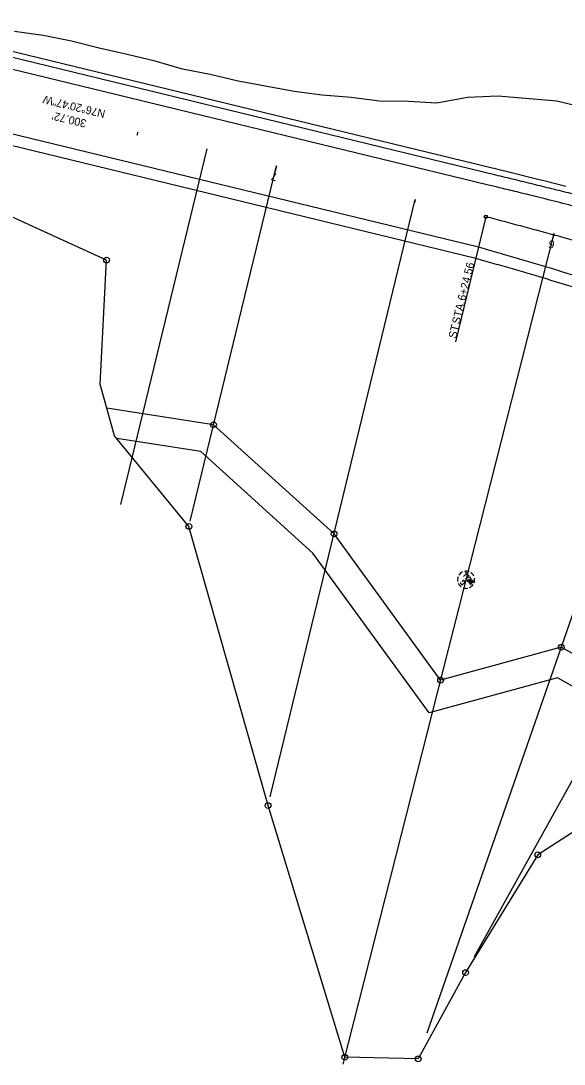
# Model space of a CAD drawing. Extents: x 2479399 to 2480150, y 287222 to 287843.
# Drawn here: x 2479690.9 to 2479881.1, y 287423.8 to 287788.8 of the extents above; entities that cross this region are included whole.
import ezdxf

# ---------------------------------------------------------------- set-up
doc = ezdxf.new("R2010")
doc.units = 0
for name, color, linetype in [('_CIVIL_CONSTRUCTION', 7, 'Continuous'), ('BD_P_Building', 7, 'Continuous'), ('GE_P_Alignment', 7, 'Continuous'), ('GE_P_Alignment_100_Curve_Data', 7, 'Continuous'), ('GE_P_Alignment_100_Distances', 7, 'Continuous'), ('GE_P_Driveway_CL', 7, 'Continuous'), ('GE_X_Alignment', 7, 'Continuous'), ('GE_X_Alignment_100_Bearings', 7, 'Continuous'), ('GE_X_Alignment_100_Curve_Data', 7, 'Continuous'), ('PF_P_Grade_Line', 7, 'Continuous'), ('PF_X_Ground_Line', 7, 'Continuous'), ('SC_Scratch1', 7, 'Continuous')]:
    doc.layers.add(name, color=color, linetype=linetype)

msp = doc.modelspace()

# ---------------------------------------------------------------- linework, layer by layer
at = {"layer": '_CIVIL_CONSTRUCTION'}
msp.add_lwpolyline([(2479881.69, 287730.89), (2479874, 287732.81), (2479871.87, 287733.34), (2479862.11, 287735.73), (2479643.48, 287788.84)], dxfattribs=at)
at = {"layer": 'BD_P_Building'}
for centre in [(2479720.89, 287705.14), (2479758.35, 287647.52), (2479749.71, 287611.94), (2479800.52, 287609.31), (2479880.04, 287569.64), (2479837.81, 287558.13), (2479777.43, 287514.24), (2479871.8, 287497), (2479846.55, 287455.78), (2479804.29, 287426.17), (2479829.98, 287425.6)]:
    msp.add_circle(centre, 1, dxfattribs=at)
at = {"layer": 'GE_P_Alignment'}
for p, q in [((2479725.85, 287619.62), (2479756.06, 287744)), ((2479750.14, 287613.72), (2479780.35, 287738.1)), ((2479778.16, 287517.26), (2479828.94, 287726.29)), ((2479803.68, 287423.76), (2479877.51, 287714.41)), ((2479833.14, 287434.7), (2479925.48, 287700.38)), ((2479849.72, 287461.48), (2479971.21, 287680.32))]:
    msp.add_line(p, q, dxfattribs=at)
msp.add_open_spline([(2479977.73, 287673.34), (2479975.86, 287674.51), (2479972.13, 287676.85), (2479966.39, 287680.15), (2479960.57, 287683.31), (2479954.65, 287686.31), (2479948.66, 287689.17), (2479942.59, 287691.89), (2479936.47, 287694.47), (2479930.29, 287696.94), (2479924.05, 287699.3), (2479917.78, 287701.54), (2479911.47, 287703.7), (2479905.12, 287705.76), (2479898.74, 287707.75), (2479892.35, 287709.67), (2479885.93, 287711.53), (2479879.49, 287713.34), (2479873.04, 287715.11), (2479866.59, 287716.85), (2479860.12, 287718.58), (2479855.81, 287719.72), (2479853.66, 287720.29)], degree=3, dxfattribs=at)
at = {"layer": 'GE_P_Alignment_100_Distances'}
msp.add_line((2479853.66, 287720.29), (2479843.04, 287676.56), dxfattribs=at)
msp.add_circle((2479853.66, 287720.29), 0.6, dxfattribs=at)
at = {"layer": 'GE_P_Driveway_CL'}
msp.add_line((2479846.73, 287593.25), (2479846.73, 287593.25), dxfattribs=at)
for points in [[(2479845.77, 287594.45), (2479846.99, 287595.48), (2479846.5, 287596.06)], [(2479844.88, 287592.31), (2479844.84, 287592.26), (2479844.82, 287592.19), (2479844.81, 287592.1), (2479844.81, 287591.99), (2479844.83, 287591.92), (2479844.85, 287591.88), (2479844.89, 287591.81), (2479844.99, 287591.69), (2479845.04, 287591.65), (2479845.07, 287591.63), (2479845.13, 287591.61), (2479845.25, 287591.58), (2479845.36, 287591.59), (2479845.46, 287591.63), (2479845.58, 287591.7), (2479845.75, 287591.81), (2479845.95, 287591.98), (2479846.11, 287592.13), (2479846.2, 287592.27), (2479846.27, 287592.43), (2479846.27, 287592.51), (2479846.25, 287592.6), (2479846.2, 287592.74), (2479846.11, 287592.84), (2479846.01, 287592.93), (2479845.95, 287592.95), (2479845.9, 287592.98), (2479845.83, 287592.98), (2479845.74, 287592.97), (2479845.62, 287592.94), (2479845.38, 287592.73), (2479845.55, 287592.53)], [(2479846.54, 287593.53), (2479847.77, 287594.56), (2479847.27, 287595.14)], [(2479846.83, 287593.19), (2479847.32, 287592.61), (2479848.54, 287593.64), (2479848.01, 287594.26)], [(2479847.92, 287593.12), (2479847.58, 287593.53)], [(2479848.23, 287591.52), (2479849.32, 287592.71), (2479847.92, 287591.89), (2479848.97, 287593.14), (2479847.6, 287592.27)]]:
    msp.add_lwpolyline(points, dxfattribs=at)
for start, end in [(114.1616, 146.1574), (69.1461, 101.173), (24.1005, 56.0962), (159.1461, 191.1173), (204.1005, 236.0962), (339.1461, 11.1173), (249.1461, 281.1173), (294.1616, 326.2186)]:
    msp.add_arc((2479846.73, 287593.25), 3, start, end, dxfattribs=at)
at = {"layer": 'GE_X_Alignment'}
for p, q in [((2479854.62, 287731.37), (2479642.05, 287783.01)), ((2479851.06, 287709.6), (2479636.85, 287761.63))]:
    msp.add_line(p, q, dxfattribs=at)
for points in [[(2479983.41, 287685.98), (2479982.19, 287686.71), (2479979.72, 287688.16), (2479974.74, 287690.96), (2479968.43, 287694.3), (2479960.72, 287698.05), (2479952.91, 287701.56), (2479944.99, 287704.85), (2479937, 287707.93), (2479928.93, 287710.83), (2479920.8, 287713.55), (2479912.63, 287716.12), (2479904.41, 287718.55), (2479896.16, 287720.87), (2479887.88, 287723.09), (2479879.58, 287725.23), (2479871.27, 287727.31), (2479864.34, 287729.01), (2479858.78, 287730.36), (2479856.01, 287731.04), (2479854.62, 287731.37)], [(2479970.57, 287661.61), (2479968.84, 287662.75), (2479965.38, 287665.03), (2479960.05, 287668.26), (2479954.61, 287671.37), (2479949.06, 287674.35), (2479943.42, 287677.2), (2479937.67, 287679.93), (2479931.85, 287682.55), (2479925.95, 287685.06), (2479919.97, 287687.47), (2479913.93, 287689.78), (2479907.83, 287692.01), (2479901.68, 287694.16), (2479895.48, 287696.24), (2479889.23, 287698.26), (2479882.95, 287700.23), (2479876.62, 287702.15), (2479870.27, 287704.04), (2479863.89, 287705.91), (2479857.48, 287707.76), (2479853.21, 287708.98), (2479851.06, 287709.6)]]:
    msp.add_open_spline(points, degree=3, dxfattribs=at)
at = {"layer": 'GE_X_Alignment_100_Bearings'}
for p, q in [((2479857.2, 287734.86), (2479642.99, 287786.9)), ((2479850.12, 287705.71), (2479635.91, 287757.75))]:
    msp.add_line(p, q, dxfattribs=at)
for points in [[(2479986.97, 287688.5), (2479984.93, 287689.72), (2479980.85, 287692.16), (2479974.61, 287695.58), (2479968.3, 287698.83), (2479961.93, 287701.89), (2479955.51, 287704.8), (2479949.04, 287707.54), (2479942.53, 287710.13), (2479936, 287712.58), (2479929.44, 287714.9), (2479922.87, 287717.11), (2479916.29, 287719.2), (2479909.7, 287721.2), (2479903.11, 287723.1), (2479896.52, 287724.93), (2479889.93, 287726.7), (2479883.36, 287728.4), (2479876.8, 287730.06), (2479870.25, 287731.68), (2479863.72, 287733.28), (2479859.37, 287734.34), (2479857.2, 287734.86)], [(2479968.48, 287658.19), (2479966.79, 287659.31), (2479963.4, 287661.55), (2479958.17, 287664.73), (2479952.83, 287667.79), (2479947.37, 287670.73), (2479941.81, 287673.54), (2479936.15, 287676.23), (2479930.4, 287678.82), (2479924.57, 287681.3), (2479918.66, 287683.69), (2479912.69, 287685.98), (2479906.64, 287688.19), (2479900.54, 287690.33), (2479894.38, 287692.39), (2479888.18, 287694.4), (2479881.92, 287696.36), (2479875.63, 287698.28), (2479869.29, 287700.16), (2479862.93, 287702.02), (2479856.53, 287703.87), (2479852.26, 287705.1), (2479850.12, 287705.71)]]:
    msp.add_open_spline(points, degree=3, dxfattribs=at)
at = {"layer": 'GE_X_Alignment_100_Curve_Data'}
for points in [[(2479889.14, 287758.18), (2479878.46, 287760.68), (2479857.88, 287762.53), (2479847.2, 287762.05), (2479836.51, 287759.98), (2479826.58, 287760.63), (2479816.37, 287760.71), (2479806.48, 287762.04), (2479796.39, 287762.87), (2479786.5, 287764.12), (2479766.92, 287767.78), (2479757.2, 287770.11), (2479747.41, 287771.96), (2479737.85, 287774.79), (2479728.04, 287777.04), (2479718.32, 287779.29), (2479708.6, 287781.78), (2479698.66, 287783.69), (2479688.68, 287785.12)], [(2479723.7, 287643.63), (2479718.68, 287661.66), (2479720.89, 287705.14), (2479674.57, 287726.24), (2479674.57, 287726.24), (2479674.57, 287726.24), (2479674.57, 287726.24), (2479674.57, 287726.24), (2479666.37, 287726.86), (2479626.33, 287739.49), (2479616.34, 287749.17), (2479616.34, 287749.17), (2479616.34, 287749.17), (2479580.2, 287761.4)], [(2479944.93, 287521.77), (2479944.93, 287521.77), (2479944.93, 287521.77), (2479917.4, 287526.22), (2479871.8, 287497), (2479846.55, 287455.78), (2479829.98, 287425.6), (2479804.29, 287426.17), (2479777.43, 287514.24), (2479749.71, 287611.94), (2479723.7, 287643.63)]]:
    msp.add_lwpolyline(points, dxfattribs=at)
at = {"layer": 'PF_P_Grade_Line'}
for p, q in [((2479731.77, 287749.9), (2479731.48, 287748.73)), ((2479780.35, 287738.1), (2479779.88, 287736.15)), ((2479828.94, 287726.29), (2479828.66, 287725.13)), ((2479877.51, 287714.41), (2479877.01, 287712.47))]:
    msp.add_line(p, q, dxfattribs=at)
at = {"layer": 'SC_Scratch1'}
for p, q in [((2479758.35, 287647.52), (2479720.99, 287653.35)), ((2479800.52, 287609.31), (2479758.35, 287647.52)), ((2479753.85, 287638.1), (2479724.45, 287642.69)), ((2479793.05, 287602.59), (2479753.85, 287638.1)), ((2479837.81, 287558.13), (2479800.52, 287609.31)), ((2479833.79, 287546.67), (2479793.05, 287602.59)), ((2479880.04, 287569.64), (2479837.81, 287558.13)), ((2479902.68, 287556.88), (2479880.04, 287569.64)), ((2479878.71, 287558.92), (2479833.79, 287546.67)), ((2479902.22, 287545.66), (2479878.71, 287558.92))]:
    msp.add_line(p, q, dxfattribs=at)

# ---------------------------------------------------------------- texts
at = {"layer": 'GE_P_Alignment_100_Curve_Data'}
msp.add_text('N76°20\'47"W', height=2.8, rotation=166.3463, dxfattribs=at).set_placement((2479720.65, 287757.54))
at = {"layer": 'GE_P_Alignment_100_Distances'}
for s, p in [('6+24.56', (2479846.43, 287690.69)), (' STA. ', (2479844.19, 287681.51)), ('ST', (2479843.22, 287677.51))]:
    msp.add_text(s, height=2.8, rotation=76.3463, dxfattribs=at).set_placement(p)
at = {"layer": 'PF_P_Grade_Line'}
for s, rotation, p in [('7', 166.3463, (2479780.91, 287735.39)), ('6', 165.7481, (2479877.98, 287711.71))]:
    msp.add_text(s, height=2.8, rotation=rotation, dxfattribs=at).set_placement(p)
at = {"layer": 'PF_X_Ground_Line'}
msp.add_text("300.72'", height=2.8, rotation=166.3463, dxfattribs=at).set_placement((2479714.03, 287754.16))

doc.saveas('drawing.dxf')
